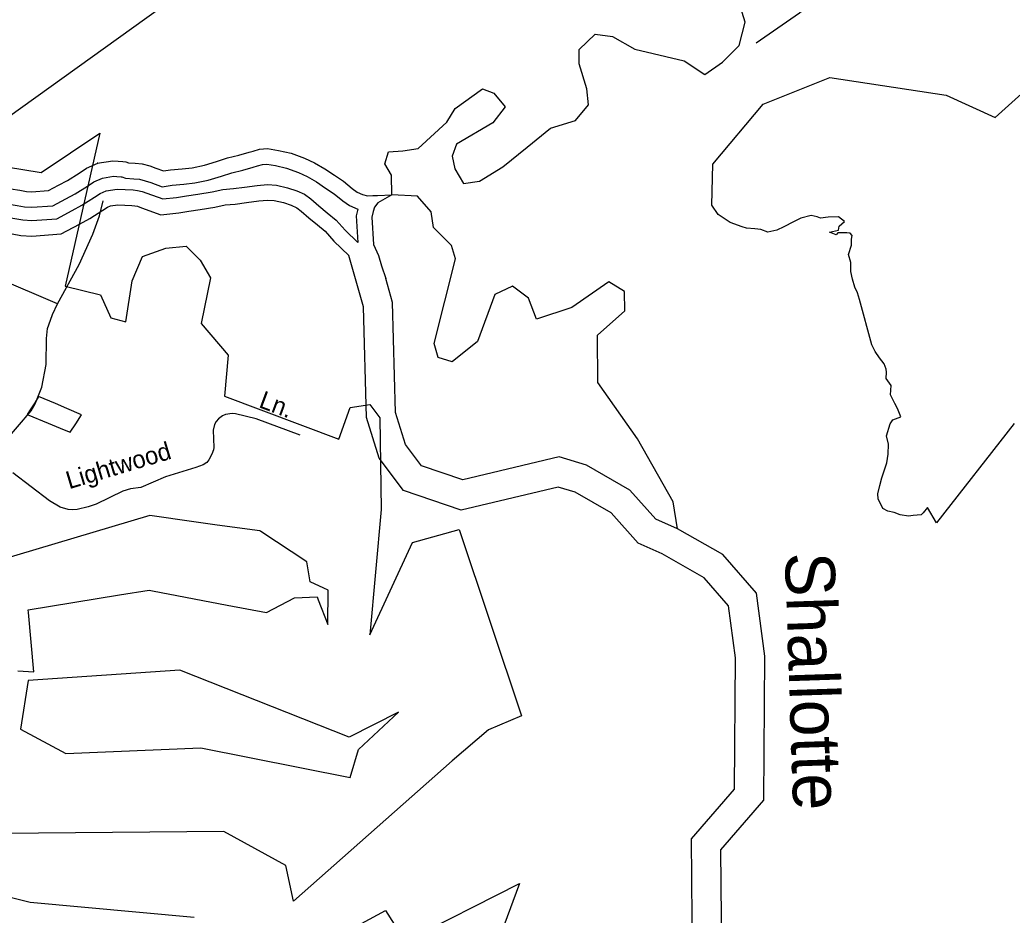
# Model space of a CAD drawing. Extents: x 2104537 to 2336408, y 34176 to 229611.
# Drawn here: x 2188998 to 2193201, y 77701 to 81491 of the extents above; entities that cross this region are included whole.
import ezdxf

# ---------------------------------------------------------------- set-up
doc = ezdxf.new("R2010")
doc.units = 0
for name, color, linetype in [('Exist Boundary Political City Limit New', 7, 'Continuous'), ('Exist Boundary Political City Limit New Hole', 7, 'Continuous'), ('Exist Hydrographic Buffer Line', 7, 'Continuous'), ('Exist Hydrographic Creek Single Shore', 7, 'Continuous'), ('Exist Hydrographic Misc Water Feature', 7, 'Continuous'), ('Exist Hydrographic River Shore', 7, 'Continuous'), ('Exist Hydrographic River Shore Label', 7, 'Continuous'), ('Exist Road Non-System Type 51', 7, 'Continuous'), ('Exist Road Non-System Type 51 Label', 7, 'Continuous'), ('Map Preparation Boundary City Limit Buffer Line', 7, 'Continuous')]:
    doc.layers.add(name, color=color, linetype=linetype)

msp = doc.modelspace()

# ---------------------------------------------------------------- linework, layer by layer
at = {"layer": 'Exist Boundary Political City Limit New'}
for points in [[(2191404.2, 85098.9), (2191321.2, 84155.2), (2191210, 84204), (2191180.2, 84220.9), (2191156.2, 84232.3), (2191149.8, 84112.5), (2191334.5, 84032.9), (2191186, 83920.8), (2191181, 83880.3), (2191236.5, 83822), (2191235, 83507.6), (2190928.5, 83479.1), (2190950, 83707.2), (2190558.2, 83315.2), (2190259, 82951.6), (2190181.5, 81963.7), (2188769.5, 80951)], [(2192514.5, 80588.1), (2192500, 80589.3), (2192463, 80589.6), (2192454.8, 80581.3), (2192426.8, 80592), (2192466, 80600.6), (2192467.8, 80618.3), (2192491.2, 80637), (2192466, 80657.6), (2192421.5, 80656), (2192389.2, 80650.9), (2192374.5, 80657.4), (2192349.5, 80662.9), (2192306, 80652.3), (2192275, 80636.7), (2192233.5, 80614.5), (2192204.2, 80600.1), (2192166.5, 80592.2), (2192136.2, 80603.2), (2192111.2, 80606.9), (2192076.2, 80609.7), (2192057.5, 80614.8), (2192006.2, 80633), (2191956, 80666.9), (2191929.2, 80706.4), (2191932.8, 80880.2), (2192145.8, 81134.2), (2192429.2, 81247.7), (2192920.8, 81172), (2193128.8, 81077.5), (2193506.8, 81417.8)], [(2188870.8, 80880.1), (2189088.2, 80844.6), (2189336.2, 81011.7), (2189190.2, 80363.1), (2189340, 80327.6), (2189383.5, 80229), (2189446.5, 80213.2), (2189474.2, 80386.8), (2189517.5, 80489.3), (2189616, 80524.8), (2189702.8, 80532.7), (2189762, 80473.5), (2189805.2, 80398.6), (2189766, 80205.3), (2189880.2, 80071.2), (2189864.5, 79897.6), (2190349.5, 79716.1), (2190396.8, 79850.3), (2190479.5, 79862.1), (2190522.8, 79806.9), (2190527.5, 79419), (2190479.5, 78887.8), (2190660.8, 79278.3), (2190858, 79333.5), (2191122, 78544.6), (2190983.5, 78486), (2190828.5, 78354.8), (2190156.2, 77759.6), (2190124, 77911.5), (2189861.8, 78054.7), (2188446.5, 78042.8)], [(2193209, 79782.3), (2192880.2, 79362), (2192842.2, 79427.3), (2192824, 79403.8), (2192815, 79395.6), (2192782, 79393.2), (2192762.5, 79390), (2192726.8, 79395.2), (2192701.8, 79405.1), (2192674.8, 79411.8), (2192652.8, 79423), (2192632.8, 79464), (2192631.5, 79484), (2192640.5, 79519.8), (2192649, 79552.1), (2192658.5, 79582.5), (2192670.5, 79616.4), (2192676.2, 79653.2), (2192677.8, 79695.1), (2192668.2, 79729.6), (2192684.8, 79781.5), (2192696.2, 79798.3), (2192730, 79809.9), (2192715, 79845.5), (2192704.2, 79867.4), (2192685, 79903.5), (2192688.5, 79943.3), (2192667.8, 79972.3), (2192668, 80000), (2192667.8, 80012.8), (2192659.2, 80034.7), (2192639.2, 80060.3), (2192620.8, 80086.6), (2192607.2, 80115.1), (2192555, 80307.8), (2192546, 80335.4), (2192534.5, 80359.6), (2192525, 80393.7), (2192518, 80426.1), (2192517.5, 80463.9), (2192507.2, 80498.1), (2192521, 80538), (2192521, 80563.4), (2192522.8, 80578.8), (2192514.5, 80588.1)], [(2188557.8, 77875.7), (2189040.8, 77756.4), (2189736.5, 77692.7)], [(2189971, 77408.5), (2190546.5, 77720.1), (2190629.2, 77590), (2191114.2, 77834.5), (2190996, 77515)]]:
    msp.add_lwpolyline(points, dxfattribs=at)
at = {"layer": 'Exist Boundary Political City Limit New Hole'}
for points in [[(2189185, 79755.8), (2189211, 79745.2), (2189235, 79780.9), (2189259, 79818.7), (2189196.2, 79845.7), (2189148.2, 79866.4), (2189076.8, 79896.8), (2189060.8, 79869.4), (2189044.2, 79844.4), (2189029, 79820.1), (2189118, 79783.3), (2189185, 79755.8)], [(2188989.2, 78734.8), (2189056.8, 78730.9), (2189033.8, 78982.6), (2189033.5, 78993.4), (2189419.2, 79057.1), (2189545.8, 79076.9), (2189560, 79074.2), (2189875.8, 79013.4), (2190041.8, 78982.4), (2190161.2, 79044.1), (2190256.8, 79048.1), (2190261.5, 79035.6), (2190302, 78931.2), (2190303.5, 79077), (2190285.8, 79085.3), (2190227.2, 79112.6), (2190213.5, 79196.2), (2190018.8, 79324.8), (2190014.8, 79327.5), (2189834, 79352.1), (2189754.8, 79363.5), (2189675.5, 79374.9), (2189607, 79384.8), (2189549, 79392.7), (2188822.2, 79176.4)], [(2189675.2, 78737.9), (2189033, 78695.1), (2189001, 78488.2), (2189192, 78384.8), (2189764.2, 78408.7), (2190396.8, 78284.2), (2190432.2, 78402.6), (2190601.8, 78560.4), (2190392.8, 78453.9), (2189675.2, 78737.9)]]:
    msp.add_lwpolyline(points, dxfattribs=at)
at = {"layer": 'Exist Hydrographic Buffer Line'}
for points in [[(2189600.1, 80784.5), (2189643.3, 80791), (2189692.3, 80794.9), (2189738.3, 80800.5), (2189795.8, 80812.1), (2189851.2, 80829.3), (2189895.4, 80843.6), (2189942.4, 80855.5), (2189986, 80867.8), (2190004.9, 80872.7), (2190024.9, 80879.1), (2190043.9, 80880.2), (2190080.7, 80874.2), (2190127.9, 80863.7), (2190178.3, 80845.3), (2190215.4, 80828.2), (2190254.5, 80805.6), (2190293, 80778.8), (2190329.1, 80754.8), (2190366.3, 80724.4), (2190393.9, 80705.1), (2190429, 80689)], [(2188794.1, 80764.5), (2188861.4, 80746.6), (2188872.2, 80742), (2188898.8, 80727), (2188944.5, 80712.1), (2188986.5, 80705.9), (2189017.3, 80699.9), (2189047.9, 80697.9), (2189138.1, 80704.4), (2189192.4, 80733.2), (2189232.4, 80755), (2189284, 80787.5), (2189311.6, 80805.5), (2189347.8, 80821.1), (2189394.3, 80828.7), (2189409.2, 80827.3), (2189427.2, 80826.4), (2189429.4, 80826.1), (2189444.9, 80820.3)], [(2189444.9, 80820.3), (2189481.1, 80818.7), (2189504.8, 80816.2), (2189529.2, 80810.2), (2189551.9, 80802.1), (2189600.1, 80784.5)], [(2189602.9, 80732.9), (2189661.4, 80738.6), (2189703.5, 80746.3), (2189752.1, 80753.4), (2189811.8, 80762.4), (2189858, 80772.6), (2189902.1, 80776.5), (2189948.8, 80783.3), (2190003.5, 80790.2), (2190046.5, 80793.8), (2190084.4, 80790.8), (2190131.9, 80780.7), (2190170.7, 80766.9), (2190202.8, 80752.6), (2190230.3, 80733.5), (2190264.3, 80703.6), (2190300.1, 80674.6), (2190337.2, 80643.7), (2190375.9, 80600.2), (2190429, 80548.1)], [(2188768.4, 80713.2), (2188845, 80692.8), (2188876, 80675.3), (2188931.5, 80657.2), (2188976.9, 80650.4), (2189010.1, 80644), (2189048.1, 80641.6), (2189154, 80649.2), (2189219, 80683.7), (2189260.8, 80706.5), (2189314.3, 80740.2), (2189338.2, 80755.7), (2189363.7, 80766.7), (2189409.3, 80774.2)], [(2189409.3, 80774.2), (2189477.6, 80771.3), (2189496.6, 80769.3), (2189515.5, 80764.6), (2189535.8, 80757.4), (2189602.9, 80732.9)], [(2190429, 80689), (2190422.5, 80660.9), (2190429, 80548.1)]]:
    msp.add_lwpolyline(points, dxfattribs=at)
at = {"layer": 'Exist Hydrographic Creek Single Shore'}
msp.add_lwpolyline([(2190573.7, 80750.6), (2190572.2, 80833.6), (2190543.4, 80881.8), (2190559.4, 80933.1), (2190620.3, 80936.3), (2190684.5, 80945.9), (2190806.3, 81058.2), (2190841.6, 81115.9), (2190957, 81199.4), (2191005.1, 81180.1), (2191053.2, 81122.4), (2191001.9, 81055), (2190848, 80965.2), (2190828.7, 80913.8), (2190839.6, 80860.3), (2190876.8, 80798.3), (2190944.2, 80808), (2191043.6, 80868.9), (2191146.2, 80952.3), (2191245.5, 81032.5), (2191351.4, 81064.6), (2191405.9, 81132), (2191399.4, 81199.4), (2191367.4, 81305.2), (2191367.4, 81366.2), (2191434.7, 81430.3), (2191508.5, 81420.7), (2191602.6, 81367.2), (2191811.6, 81317.2), (2191899.6, 81260.3), (2191973.4, 81311.6), (2192043.9, 81382.2), (2192069.6, 81481.7), (2192031.1, 81610)], dxfattribs=at)
at = {"layer": 'Exist Hydrographic Misc Water Feature'}
msp.add_lwpolyline([(2191783.7, 79336.2), (2191765.6, 79451.3), (2191613.7, 79716.8), (2191445.5, 79956.2), (2191444.5, 80156.3), (2191560.6, 80259.1), (2191559.6, 80341.1), (2191492.7, 80381.8), (2191335.6, 80273.3), (2191185.5, 80223.7), (2191151.7, 80312.9), (2191084.7, 80363.4), (2191009.6, 80328.8), (2190936.6, 80130.1), (2190828.5, 80043.6), (2190769.7, 80061.1), (2190752.7, 80120.5), (2190842.7, 80479.6), (2190825.7, 80535.8), (2190749.6, 80612.7), (2190740.6, 80678.5), (2190682.5, 80745.2), (2190573.7, 80750.6)], dxfattribs=at)
at = {"layer": 'Exist Hydrographic River Shore'}
for points in [[(2189606.8, 80851.9), (2189635.8, 80856.3), (2189685.7, 80860.2), (2189727.8, 80865.3), (2189779.5, 80875.8), (2189831.4, 80891.9), (2189877.3, 80906.7), (2189925.4, 80918.9), (2189968.9, 80931.2), (2189986.7, 80935.8), (2190012.8, 80944.1), (2190047.3, 80946.1), (2190093.1, 80938.6), (2190146.3, 80926.8), (2190203.4, 80906), (2190245.6, 80886.5), (2190289.8, 80861), (2190329.9, 80833), (2190368.1, 80807.7), (2190405.9, 80776.8), (2190426.6, 80762.3), (2190449.1, 80752), (2190470.9, 80746.6)], [(2188802.8, 80830.1), (2188882.8, 80808.9), (2188901.3, 80801), (2188925.4, 80787.4), (2188959.6, 80776.2), (2188997.5, 80770.6), (2189025.7, 80765.1), (2189047.6, 80763.7), (2189119.6, 80768.9), (2189161.3, 80791), (2189199.1, 80811.6), (2189248.6, 80842.8), (2189280.5, 80863.5), (2189327.8, 80883.9), (2189325.9, 80884), (2189392, 80894.9), (2189414, 80892.8), (2189434, 80891.7), (2189446.1, 80889.9), (2189458.1, 80885.4)], [(2189458.1, 80885.4), (2189486, 80884.2), (2189516.1, 80881), (2189548.1, 80873.1), (2189574.2, 80863.8), (2189606.8, 80851.9)], [(2190470.9, 80746.6), (2190492.9, 80747.2), (2190512, 80747.4), (2190573.7, 80750.6)], [(2190573.7, 80750.6), (2190513.9, 80716.4), (2190499.8, 80697.6), (2190494.2, 80679.7), (2190488.5, 80655.3), (2190495.2, 80540.5)], [(2188755.3, 80648.8), (2188820.1, 80631.6), (2188849.4, 80615), (2188916.4, 80593.1), (2188965.8, 80585.8), (2189001.7, 80578.8), (2189048.3, 80575.8), (2189172.5, 80584.7), (2189250.1, 80625.9), (2189294.1, 80649.9), (2189349.7, 80684.9), (2189369.3, 80697.7), (2189382.3, 80703.3), (2189413.2, 80708.4)], [(2189413.2, 80708.4), (2189472.7, 80705.8), (2189485.3, 80704.5), (2189496.7, 80701.7), (2189513.5, 80695.7), (2189594.5, 80666.1)], [(2189594.5, 80666.1), (2189670.5, 80673.6), (2189714.1, 80681.5), (2189761.7, 80688.5), (2189823.8, 80697.9), (2189868, 80707.6), (2189909.7, 80711.3), (2189957.7, 80718.3), (2190010.3, 80724.9), (2190046.7, 80727.9), (2190075, 80725.7), (2190114, 80717.4), (2190146.4, 80706), (2190170.4, 80695.2), (2190189.8, 80681.8), (2190222, 80653.5), (2190258.4, 80623.9), (2190291.5, 80596.4), (2190328.4, 80554.9), (2190391.5, 80493)], [(2190495.2, 80540.5), (2190517.6, 80493.1), (2190529.8, 80449.6), (2190547.6, 80395.9)], [(2191718.1, 79230.1), (2191617, 79275.3), (2191502.7, 79403.7), (2191349.4, 79491.8), (2191278, 79513.2), (2190867.7, 79415.6), (2190622.9, 79498.3), (2190519.1, 79635.8), (2190465.5, 79808.1), (2190453.4, 80275.7), (2190391.5, 80493)], [(2191783.7, 79336.2), (2191691.6, 79377.3), (2191581.7, 79500.8), (2191398.6, 79606.1), (2191281.7, 79641.1), (2190873.7, 79544), (2190698.5, 79603.2), (2190630.7, 79693.1), (2190588.6, 79828.4), (2190576.5, 80294.5), (2190547.6, 80395.9)], [(2192097.6, 77279.6), (2191970.7, 77544.5), (2191967.6, 77977.6), (2192149.7, 78187.4), (2192153.6, 78797.5), (2192118.7, 79063.9), (2191975.6, 79227.4), (2191783.7, 79336.2)], [(2191975.1, 77247), (2191846.3, 77515.8), (2191842.7, 78023.8), (2192025.4, 78234.2), (2192028.9, 78789.8), (2192000.1, 79010.3), (2191895.8, 79129.5), (2191718.1, 79230.1)]]:
    msp.add_lwpolyline(points, dxfattribs=at)
at = {"layer": 'Exist Road Non-System Type 51'}
msp.add_line((2189157.6, 80288.7), (2188863.1, 80413.8), dxfattribs=at)
for points in [[(2192116, 81394.3), (2192300.5, 81520.7), (2192347.9, 81561.1), (2192415.5, 81630.7), (2192432.8, 81644.4), (2192458.4, 81660.7), (2192480.5, 81667.1), (2192551.3, 81682.8), (2192571.4, 81684.1), (2192588.4, 81680.5), (2192622.6, 81669), (2192646.7, 81657.4), (2192729.4, 81608.2), (2192756.7, 81597.2), (2192803.1, 81587.7), (2192911.6, 81600.4), (2193009.5, 81605.7), (2193087.4, 81613.1), (2193207.5, 81612.4)], [(2189157.6, 80288.7), (2189249.1, 80454.9), (2189306.7, 80583.4), (2189334.5, 80661.3), (2189350.1, 80725.6)], [(2189127, 80219.9), (2189135.8, 80244.5), (2189157.6, 80288.7)], [(2188929.7, 79700), (2189045.6, 79836.2), (2189063.2, 79866.3), (2189091.1, 79936.3), (2189108.7, 80032.5), (2189110.2, 80142.7), (2189114.3, 80184.6), (2189127, 80219.9)], [(2190185, 79733.1), (2189998.3, 79802.7), (2189911.8, 79823.7), (2189896.4, 79824.3), (2189868.4, 79820.6), (2189856.2, 79814.9), (2189839.5, 79802.1), (2189829.1, 79791.2), (2189821.7, 79778.2), (2189816.6, 79754.4), (2189819.8, 79680.5), (2189818, 79671), (2189811, 79652.1), (2189798.4, 79628.4), (2189789.4, 79617.1), (2189774.7, 79607.8), (2189743, 79596), (2189615.3, 79556.1), (2189510.7, 79511.9), (2189466.7, 79505.5), (2189434.6, 79495.7), (2189320.7, 79441.1), (2189287, 79428.9), (2189240.9, 79418.7), (2189220.9, 79416.8), (2189202.8, 79418.8), (2189168.9, 79428.6), (2189122.8, 79454.4), (2188968.3, 79573.9)]]:
    msp.add_lwpolyline(points, dxfattribs=at)
at = {"layer": 'Map Preparation Boundary City Limit Buffer Line'}
for points in [[(2191404.2, 85098.9), (2191321.2, 84155.2), (2191210, 84204), (2191180.2, 84220.9), (2191156.2, 84232.3), (2191149.8, 84112.5), (2191334.5, 84032.9), (2191186, 83920.8), (2191181, 83880.3), (2191236.5, 83822), (2191235, 83507.6), (2190928.5, 83479.1), (2190950, 83707.2), (2190558.2, 83315.2), (2190259, 82951.6), (2190181.5, 81963.7), (2188769.5, 80951)], [(2192514.5, 80588.1), (2192500, 80589.3), (2192463, 80589.6), (2192454.8, 80581.3), (2192426.8, 80592), (2192466, 80600.6), (2192467.8, 80618.3), (2192491.2, 80637), (2192466, 80657.6), (2192421.5, 80656), (2192389.2, 80650.9), (2192374.5, 80657.4), (2192349.5, 80662.9), (2192306, 80652.3), (2192275, 80636.7), (2192233.5, 80614.5), (2192204.2, 80600.1), (2192166.5, 80592.2), (2192136.2, 80603.2), (2192111.2, 80606.9), (2192076.2, 80609.7), (2192057.5, 80614.8), (2192006.2, 80633), (2191956, 80666.9), (2191929.2, 80706.4), (2191932.8, 80880.2), (2192145.8, 81134.2), (2192429.2, 81247.7), (2192920.8, 81172), (2193128.8, 81077.5), (2193506.8, 81417.8)], [(2188870.8, 80880.1), (2189088.2, 80844.6), (2189336.2, 81011.7), (2189190.2, 80363.1), (2189340, 80327.6), (2189383.5, 80229), (2189446.5, 80213.2), (2189474.2, 80386.8), (2189517.5, 80489.3), (2189616, 80524.8), (2189702.8, 80532.7), (2189762, 80473.5), (2189805.2, 80398.6), (2189766, 80205.3), (2189880.2, 80071.2), (2189864.5, 79897.6), (2190349.5, 79716.1), (2190396.8, 79850.3), (2190479.5, 79862.1), (2190522.8, 79806.9), (2190527.5, 79419), (2190479.5, 78887.8), (2190660.8, 79278.3), (2190858, 79333.5), (2191122, 78544.6), (2190983.5, 78486), (2190828.5, 78354.8), (2190156.2, 77759.6), (2190124, 77911.5), (2189861.8, 78054.7), (2188446.5, 78042.8)], [(2193209, 79782.3), (2192880.2, 79362), (2192842.2, 79427.3), (2192824, 79403.8), (2192815, 79395.6), (2192782, 79393.2), (2192762.5, 79390), (2192726.8, 79395.2), (2192701.8, 79405.1), (2192674.8, 79411.8), (2192652.8, 79423), (2192632.8, 79464), (2192631.5, 79484), (2192640.5, 79519.8), (2192649, 79552.1), (2192658.5, 79582.5), (2192670.5, 79616.4), (2192676.2, 79653.2), (2192677.8, 79695.1), (2192668.2, 79729.6), (2192684.8, 79781.5), (2192696.2, 79798.3), (2192730, 79809.9), (2192715, 79845.5), (2192704.2, 79867.4), (2192685, 79903.5), (2192688.5, 79943.3), (2192667.8, 79972.3), (2192668, 80000), (2192667.8, 80012.8), (2192659.2, 80034.7), (2192639.2, 80060.3), (2192620.8, 80086.6), (2192607.2, 80115.1), (2192555, 80307.8), (2192546, 80335.4), (2192534.5, 80359.6), (2192525, 80393.7), (2192518, 80426.1), (2192517.5, 80463.9), (2192507.2, 80498.1), (2192521, 80538), (2192521, 80563.4), (2192522.8, 80578.8), (2192514.5, 80588.1)], [(2189185, 79755.8), (2189211, 79745.2), (2189235, 79780.9), (2189259, 79818.7), (2189196.2, 79845.7), (2189148.2, 79866.4), (2189076.8, 79896.8), (2189060.8, 79869.4), (2189044.2, 79844.4), (2189029, 79820.1), (2189118, 79783.3), (2189185, 79755.8)], [(2188989.2, 78734.8), (2189056.8, 78730.9), (2189033.8, 78982.6), (2189033.5, 78993.4), (2189419.2, 79057.1), (2189545.8, 79076.9), (2189560, 79074.2), (2189875.8, 79013.4), (2190041.8, 78982.4), (2190161.2, 79044.1), (2190256.8, 79048.1), (2190261.5, 79035.6), (2190302, 78931.2), (2190303.5, 79077), (2190285.8, 79085.3), (2190227.2, 79112.6), (2190213.5, 79196.2), (2190018.8, 79324.8), (2190014.8, 79327.5), (2189834, 79352.1), (2189754.8, 79363.5), (2189675.5, 79374.9), (2189607, 79384.8), (2189549, 79392.7), (2188822.2, 79176.4)], [(2189675.2, 78737.9), (2189033, 78695.1), (2189001, 78488.2), (2189192, 78384.8), (2189764.2, 78408.7), (2190396.8, 78284.2), (2190432.2, 78402.6), (2190601.8, 78560.4), (2190392.8, 78453.9), (2189675.2, 78737.9)], [(2188557.8, 77875.7), (2189040.8, 77756.4), (2189736.5, 77692.7)], [(2189971, 77408.5), (2190546.5, 77720.1), (2190629.2, 77590), (2191114.2, 77834.5), (2190996, 77515)]]:
    msp.add_lwpolyline(points, dxfattribs=at)

# ---------------------------------------------------------------- texts
at = {"layer": 'Exist Hydrographic River Shore Label'}
msp.add_text('Shallotte', height=210, rotation=271.9008, dxfattribs=at).set_placement((2192238, 79234.5))
at = {"layer": 'Exist Road Non-System Type 51 Label'}
for s, rotation, p in [('Ln.', 339.5639, (2190006, 79852.3)), ('Lightwood', 16.5885, (2189206.5, 79503.9))]:
    msp.add_text(s, height=75, rotation=rotation, dxfattribs=at).set_placement(p)

doc.saveas('drawing.dxf')
